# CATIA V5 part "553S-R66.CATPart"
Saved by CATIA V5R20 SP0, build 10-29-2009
Part number: 553S-R66
Definition: NONE
Nomenclature: 553S-R66
Source: Unknown
Description: 553S-R66
Bounding box of the stored display mesh (mm): x -34.75 to 34.75, y -36.41 to 36.592, z -1.25 to 1.25
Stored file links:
  C:\Users\Utente\Desktop\IO LAVORO\3D X SITO CF\X SITO\PLASTICA\553S\553S-R66.CATPart
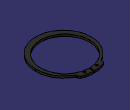
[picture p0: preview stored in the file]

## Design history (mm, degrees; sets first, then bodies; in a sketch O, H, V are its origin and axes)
Body1 "553S-R66" (main body)
  Solid1: solid without history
